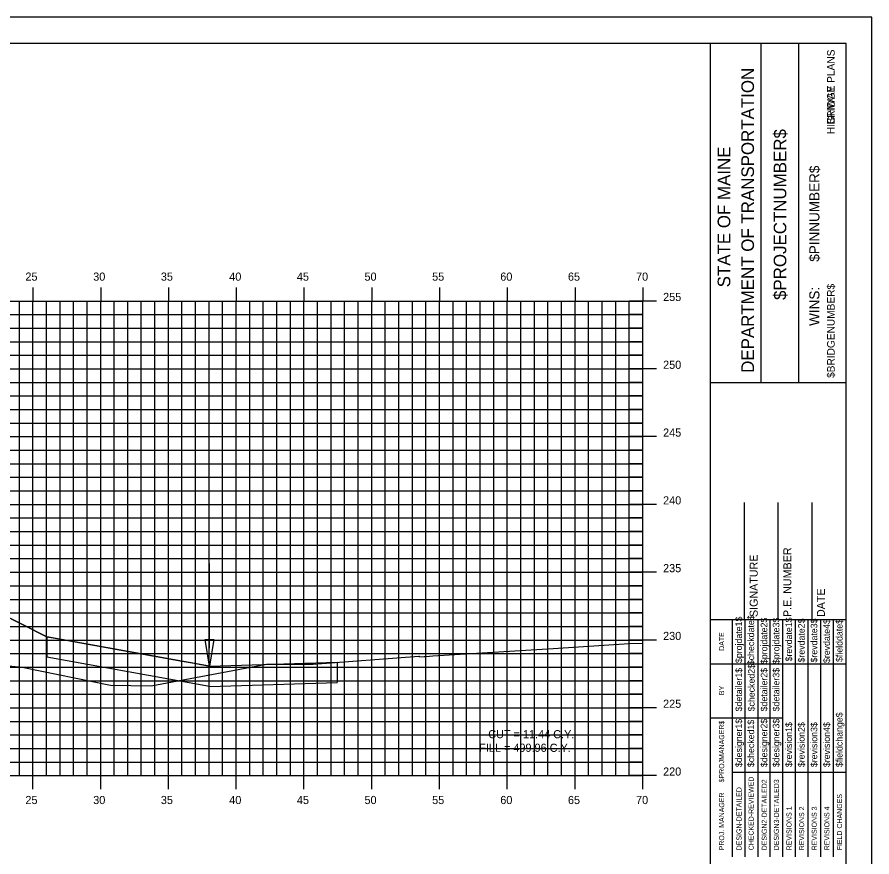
# Model space of a CAD drawing. Extents: x -22 to 1480, y -1511 to 8.
# Drawn here: x 877.3 to 940.3, y -1463.3 to -1401.4 of the extents above; entities that cross this region are included whole.
import ezdxf

# ---------------------------------------------------------------- set-up
doc = ezdxf.new("R2010")
doc.units = 0
for name, color, linetype in [('ANNOTATION', 7, 'Continuous'), ('BORDER', 7, 'Continuous'), ('BRIDGE_TITLE', 7, 'Continuous'), ('D_Drainage_Ditch_Line', 7, 'Continuous'), ('D_Roadway_Centerline', 7, 'Continuous'), ('D_Roadway_SlopeLines', 7, 'Continuous'), ('H_V ANNOTATION', 7, 'Continuous'), ('HIGHWAY_TITLE', 7, 'Continuous'), ('MAJOR', 7, 'Continuous'), ('MINOR', 7, 'Continuous'), ('PLOT BOUNDARY', 7, 'Continuous'), ('S_Roadway_Centerline', 7, 'Continuous')]:
    doc.layers.add(name, color=color, linetype=linetype)

msp = doc.modelspace()

# ---------------------------------------------------------------- linework, layer by layer
at = {"layer": 'BORDER'}
for p, q in [((938.426, -1403.331), (778.426, -1403.331)), ((928.426, -1508.328), (928.426, -1403.328)), ((932.155, -1428.334), (932.155, -1403.334)), ((934.95, -1428.334), (934.95, -1403.334)), ((938.426, -1508.328), (938.426, -1403.328)), ((928.427, -1428.337), (938.426, -1428.337)), ((930.926, -1445.828), (930.926, -1437.181)), ((933.426, -1445.828), (933.426, -1437.181)), ((935.926, -1445.828), (935.926, -1437.181)), ((928.426, -1445.828), (938.426, -1445.828))]:
    msp.add_line(p, q, dxfattribs=at)
for points in [[(930.041, -1449.078), (930.041, -1445.828)], [(930.974, -1463.325), (930.974, -1445.828)], [(931.905, -1445.828), (931.905, -1463.325)], [(932.837, -1463.325), (932.837, -1445.828)], [(933.769, -1463.325), (933.769, -1445.828)], [(934.7, -1463.325), (934.7, -1445.828)], [(935.632, -1463.325), (935.632, -1445.828)], [(936.564, -1463.325), (936.564, -1445.828)], [(937.495, -1463.325), (937.495, -1445.828)], [(930.042, -1463.325), (930.042, -1446.534)], [(928.426, -1449.078), (938.426, -1449.078)], [(928.426, -1453.078), (930.042, -1453.078)], [(930.041, -1453.078), (933.768, -1453.078)], [(930.041, -1457.078), (938.426, -1457.078)]]:
    msp.add_lwpolyline(points, dxfattribs=at)
at = {"layer": 'D_Drainage_Ditch_Line'}
msp.add_line((891.456, -1447.94), (891.456, -1441.697), dxfattribs=at)
msp.add_lwpolyline([(891.128, -1447.284), (891.784, -1447.284), (891.456, -1449.252)], close=True, dxfattribs=at)
at = {"layer": 'D_Roadway_Centerline'}
msp.add_lwpolyline([(874.083, -1444.402), (879.451, -1447.086), (880.06, -1447.196), (885.062, -1448.098), (889.433, -1448.888), (890.33, -1449.05), (891.456, -1449.252), (900.867, -1448.972)], dxfattribs=at)
at = {"layer": 'D_Roadway_SlopeLines'}
for p, q in [((879.451, -1447.086), (874.083, -1444.402)), ((879.451, -1447.086), (879.451, -1448.586)), ((900.867, -1448.972), (900.867, -1450.47)), ((891.456, -1450.752), (900.867, -1450.47))]:
    msp.add_line(p, q, dxfattribs=at)
for points in [[(891.456, -1449.252), (879.451, -1447.086)], [(891.456, -1449.252), (879.451, -1447.086)], [(891.456, -1450.752), (879.451, -1448.586)]]:
    msp.add_lwpolyline(points, dxfattribs=at)
at = {"layer": 'MAJOR'}
for p, q in [((878.426, -1421.329), (878.426, -1422.331)), ((883.426, -1421.329), (883.426, -1422.331)), ((888.426, -1421.329), (888.426, -1422.331)), ((893.426, -1421.329), (893.426, -1422.331)), ((898.426, -1421.329), (898.426, -1422.331)), ((903.426, -1421.329), (903.426, -1422.331)), ((908.426, -1421.329), (908.426, -1422.331)), ((913.426, -1421.329), (913.426, -1422.331)), ((918.426, -1421.329), (918.426, -1422.331)), ((923.426, -1421.329), (923.426, -1422.331)), ((783.426, -1422.331), (923.426, -1422.331)), ((783.426, -1422.331), (923.426, -1422.331)), ((878.426, -1457.331), (878.426, -1422.331)), ((883.426, -1457.331), (883.426, -1422.331)), ((888.426, -1457.331), (888.426, -1422.331)), ((893.426, -1457.331), (893.426, -1422.331)), ((898.426, -1457.331), (898.426, -1422.331)), ((903.426, -1457.331), (903.426, -1422.331)), ((908.426, -1457.331), (908.426, -1422.331)), ((913.426, -1457.331), (913.426, -1422.331)), ((918.426, -1457.331), (918.426, -1422.331)), ((924.428, -1422.331), (922.424, -1422.331)), ((923.426, -1457.331), (923.426, -1422.331)), ((923.426, -1457.331), (923.426, -1422.331)), ((783.426, -1427.331), (923.426, -1427.331)), ((924.428, -1427.331), (922.424, -1427.331)), ((783.426, -1432.331), (923.426, -1432.331)), ((924.428, -1432.331), (922.424, -1432.331)), ((783.426, -1437.331), (923.426, -1437.331)), ((924.428, -1437.331), (922.424, -1437.331)), ((783.426, -1442.331), (923.426, -1442.331)), ((924.428, -1442.331), (922.424, -1442.331)), ((783.426, -1447.331), (923.426, -1447.331)), ((924.428, -1447.331), (922.424, -1447.331)), ((783.426, -1452.331), (923.426, -1452.331)), ((924.428, -1452.331), (922.424, -1452.331)), ((783.426, -1457.331), (923.426, -1457.331)), ((783.426, -1457.331), (923.426, -1457.331)), ((878.426, -1458.333), (878.426, -1457.331)), ((883.426, -1458.333), (883.426, -1457.331)), ((888.426, -1458.333), (888.426, -1457.331)), ((893.426, -1458.333), (893.426, -1457.331)), ((898.426, -1458.333), (898.426, -1457.331)), ((903.426, -1458.333), (903.426, -1457.331)), ((908.426, -1458.333), (908.426, -1457.331)), ((913.426, -1458.333), (913.426, -1457.331)), ((918.426, -1458.333), (918.426, -1457.331)), ((924.428, -1457.331), (922.424, -1457.331)), ((923.426, -1458.333), (923.426, -1457.331))]:
    msp.add_line(p, q, dxfattribs=at)
at = {"layer": 'MINOR'}
for p, q in [((877.426, -1457.331), (877.426, -1422.331)), ((879.426, -1457.331), (879.426, -1422.331)), ((880.426, -1457.331), (880.426, -1422.331)), ((881.426, -1457.331), (881.426, -1422.331)), ((882.426, -1457.331), (882.426, -1422.331)), ((884.426, -1457.331), (884.426, -1422.331)), ((885.426, -1457.331), (885.426, -1422.331)), ((886.426, -1457.331), (886.426, -1422.331)), ((887.426, -1457.331), (887.426, -1422.331)), ((889.426, -1457.331), (889.426, -1422.331)), ((890.426, -1457.331), (890.426, -1422.331)), ((891.426, -1457.331), (891.426, -1422.331)), ((892.426, -1457.331), (892.426, -1422.331)), ((894.426, -1457.331), (894.426, -1422.331)), ((895.426, -1457.331), (895.426, -1422.331)), ((896.426, -1457.331), (896.426, -1422.331)), ((897.426, -1457.331), (897.426, -1422.331)), ((899.426, -1457.331), (899.426, -1422.331)), ((900.426, -1457.331), (900.426, -1422.331)), ((901.426, -1457.331), (901.426, -1422.331)), ((902.426, -1457.331), (902.426, -1422.331)), ((904.426, -1457.331), (904.426, -1422.331)), ((905.426, -1457.331), (905.426, -1422.331)), ((906.426, -1457.331), (906.426, -1422.331)), ((907.426, -1457.331), (907.426, -1422.331)), ((909.426, -1457.331), (909.426, -1422.331)), ((910.426, -1457.331), (910.426, -1422.331)), ((911.426, -1457.331), (911.426, -1422.331)), ((912.426, -1457.331), (912.426, -1422.331)), ((914.426, -1457.331), (914.426, -1422.331)), ((915.426, -1457.331), (915.426, -1422.331)), ((916.426, -1457.331), (916.426, -1422.331)), ((917.426, -1457.331), (917.426, -1422.331)), ((919.426, -1457.331), (919.426, -1422.331)), ((920.426, -1457.331), (920.426, -1422.331)), ((921.426, -1457.331), (921.426, -1422.331)), ((922.426, -1457.331), (922.426, -1422.331)), ((783.426, -1423.331), (923.426, -1423.331)), ((923.426, -1423.331), (922.424, -1423.331)), ((783.426, -1424.331), (923.426, -1424.331)), ((923.426, -1424.331), (922.424, -1424.331)), ((783.426, -1425.331), (923.426, -1425.331)), ((923.426, -1425.331), (922.424, -1425.331)), ((783.426, -1426.331), (923.426, -1426.331)), ((923.426, -1426.331), (922.424, -1426.331)), ((783.426, -1428.331), (923.426, -1428.331)), ((923.426, -1428.331), (922.424, -1428.331)), ((783.426, -1429.331), (923.426, -1429.331)), ((923.426, -1429.331), (922.424, -1429.331)), ((783.426, -1430.331), (923.426, -1430.331)), ((923.426, -1430.331), (922.424, -1430.331)), ((783.426, -1431.331), (923.426, -1431.331)), ((923.426, -1431.331), (922.424, -1431.331)), ((783.426, -1433.331), (923.426, -1433.331)), ((923.426, -1433.331), (922.424, -1433.331)), ((783.426, -1434.331), (923.426, -1434.331)), ((923.426, -1434.331), (922.424, -1434.331)), ((783.426, -1435.331), (923.426, -1435.331)), ((923.426, -1435.331), (922.424, -1435.331)), ((783.426, -1436.331), (923.426, -1436.331)), ((923.426, -1436.331), (922.424, -1436.331)), ((783.426, -1438.331), (923.426, -1438.331)), ((923.426, -1438.331), (922.424, -1438.331)), ((783.426, -1439.331), (923.426, -1439.331)), ((923.426, -1439.331), (922.424, -1439.331)), ((783.426, -1440.331), (923.426, -1440.331)), ((923.426, -1440.331), (922.424, -1440.331)), ((783.426, -1441.331), (923.426, -1441.331)), ((923.426, -1441.331), (922.424, -1441.331)), ((783.426, -1443.331), (923.426, -1443.331)), ((923.426, -1443.331), (922.424, -1443.331)), ((783.426, -1444.331), (923.426, -1444.331)), ((923.426, -1444.331), (922.424, -1444.331)), ((783.426, -1445.331), (923.426, -1445.331)), ((923.426, -1445.331), (922.424, -1445.331)), ((783.426, -1446.331), (923.426, -1446.331)), ((923.426, -1446.331), (922.424, -1446.331)), ((783.426, -1448.331), (923.426, -1448.331)), ((923.426, -1448.331), (922.424, -1448.331)), ((783.426, -1449.331), (923.426, -1449.331)), ((923.426, -1449.331), (922.424, -1449.331)), ((783.426, -1450.331), (923.426, -1450.331)), ((923.426, -1450.331), (922.424, -1450.331)), ((783.426, -1451.331), (923.426, -1451.331)), ((923.426, -1451.331), (922.424, -1451.331)), ((783.426, -1453.331), (923.426, -1453.331)), ((923.426, -1453.331), (922.424, -1453.331)), ((783.426, -1454.331), (923.426, -1454.331)), ((923.426, -1454.331), (922.424, -1454.331)), ((783.426, -1455.331), (923.426, -1455.331)), ((923.426, -1455.331), (922.424, -1455.331)), ((783.426, -1456.331), (923.426, -1456.331)), ((923.426, -1456.331), (922.424, -1456.331))]:
    msp.add_line(p, q, dxfattribs=at)
at = {"layer": 'PLOT BOUNDARY'}
msp.add_lwpolyline([(770.333, -1511.39), (940.333, -1511.39), (940.333, -1401.39), (770.333, -1401.39)], close=True, dxfattribs=at)
at = {"layer": 'S_Roadway_Centerline'}
msp.add_lwpolyline([(873.038, -1448.9), (877.633, -1449.335), (884.159, -1450.673), (887.145, -1450.704), (895.653, -1449.11), (899.11, -1449.102), (906.906, -1448.528), (906.939, -1448.533), (906.966, -1448.562), (907.287, -1448.547), (907.447, -1448.536), (907.929, -1448.503), (907.932, -1448.503), (916.802, -1447.957), (922.425, -1447.583), (923.426, -1447.574)], dxfattribs=at)
msp.add_lwpolyline([(873.038, -1448.9), (877.633, -1449.335), (884.159, -1450.673), (887.145, -1450.704), (895.653, -1449.11), (899.11, -1449.102), (906.906, -1448.528), (906.939, -1448.533), (906.966, -1448.562), (907.287, -1448.547), (907.447, -1448.536), (907.929, -1448.503), (907.932, -1448.503), (916.802, -1447.957), (922.425, -1447.583), (923.426, -1447.574)], dxfattribs=at)

# ---------------------------------------------------------------- texts
at = {"layer": 'ANNOTATION'}
for s, p in [('CUT = 11.44 C.Y.', (912.024, -1454.571)), ('FILL = 499.96 C.Y.', (911.359, -1455.572))]:
    msp.add_text(s, height=0.6, rotation=359.92408, dxfattribs=at).set_placement(p)
at = {"layer": 'BORDER'}
for s, height, p in [('DEPARTMENT OF TRANSPORTATION', 0.93176, (931.633, -1427.625)), ('$PROJECTNUMBER$', 0.93176, (934.018, -1422.252)), ('STATE OF MAINE', 0.93176, (929.882, -1421.319)), ('$PINNUMBER$', 0.74527, (936.463, -1419.434)), ('WINS:', 0.7453, (936.461, -1424.164)), ('P.E. NUMBER', 0.59055, (934.387, -1445.636)), ('SIGNATURE', 0.5906, (931.907, -1445.636)), ('DATE', 0.5906, (936.867, -1445.636)), ('$projdate1$', 0.48455, (930.749, -1449.028)), ('$checkdate$', 0.48455, (931.644, -1449.186)), ('$projdate2$', 0.48455, (932.613, -1449.107)), ('$projdate3$', 0.48455, (933.507, -1449.107)), ('$revdate1$', 0.4845, (934.439, -1448.91)), ('$revdate2$', 0.4845, (935.37, -1448.989)), ('$revdate3$', 0.4845, (936.302, -1448.989)), ('$revdate4$', 0.4845, (937.234, -1449.028)), ('$fielddate$', 0.48455, (938.165, -1448.949)), ('DATE', 0.3714, (929.431, -1448.123)), ('$detailer1$', 0.48455, (930.749, -1452.593)), ('$checked2$', 0.4845, (931.681, -1452.593)), ('$detailer2$', 0.48455, (932.613, -1452.593)), ('$detailer3$', 0.48455, (933.507, -1452.593)), ('BY', 0.3714, (929.431, -1451.393)), ('$designer1$', 0.48455, (930.749, -1456.705)), ('$designer2$', 0.48455, (932.613, -1456.705)), ('$designer3$', 0.48455, (933.507, -1456.705)), ('$fieldchange$', 0.48455, (938.165, -1456.705)), ('$PROJMANAGER$', 0.37275, (929.431, -1457.833)), ('$checked1$', 0.4845, (931.644, -1456.705)), ('$revision1$', 0.48455, (934.439, -1456.705)), ('$revision2$', 0.48455, (935.37, -1456.705)), ('$revision3$', 0.48455, (936.302, -1456.705)), ('$revision4$', 0.48455, (937.234, -1456.705)), ('CHECKED-REVIEWED', 0.37275, (931.607, -1462.84)), ('DESIGN2-DETAILED2', 0.37275, (932.576, -1462.84)), ('DESIGN3-DETAILED3', 0.37275, (933.471, -1462.84)), ('PROJ. MANAGER', 0.37275, (929.431, -1462.84)), ('DESIGN-DETAILED', 0.37275, (930.713, -1462.84)), ('FIELD CHANGES', 0.37275, (938.129, -1462.84)), ('REVISIONS 1', 0.37275, (934.402, -1462.84)), ('REVISIONS 2', 0.37275, (935.334, -1462.84)), ('REVISIONS 3', 0.37275, (936.266, -1462.84)), ('REVISIONS 4', 0.37275, (937.197, -1462.84))]:
    msp.add_text(s, height=height, rotation=90, dxfattribs=at).set_placement(p)
at = {"layer": 'BRIDGE_TITLE'}
for s, p in [('BRIDGE PLANS', (937.585, -1409.307)), ('$BRIDGENUMBER$', (937.585, -1428.001))]:
    msp.add_text(s, height=0.55901, rotation=90, dxfattribs=at).set_placement(p)
at = {"layer": 'H_V ANNOTATION'}
for s, p in [('25', (877.872, -1420.831)), ('30', (882.875, -1420.831)), ('35', (887.867, -1420.831)), ('40', (892.912, -1420.831)), ('45', (897.904, -1420.831)), ('50', (902.891, -1420.831)), ('55', (907.883, -1420.831)), ('60', (912.912, -1420.831)), ('65', (917.904, -1420.831)), ('70', (922.928, -1420.831)), ('255', (924.926, -1422.331)), ('250', (924.926, -1427.331)), ('245', (924.926, -1432.331)), ('240', (924.926, -1437.331)), ('235', (924.926, -1442.331)), ('230', (924.926, -1447.331)), ('225', (924.926, -1452.331)), ('220', (924.926, -1457.331)), ('25', (877.872, -1459.431)), ('30', (882.875, -1459.431)), ('35', (887.867, -1459.431)), ('40', (892.912, -1459.431)), ('45', (897.904, -1459.431)), ('50', (902.891, -1459.431)), ('55', (907.883, -1459.431)), ('60', (912.912, -1459.431)), ('65', (917.904, -1459.431)), ('70', (922.928, -1459.431))]:
    msp.add_text(s, height=0.6, dxfattribs=at).set_placement(p)
at = {"layer": 'HIGHWAY_TITLE'}
msp.add_text('HIGHWAY PLANS', height=0.55901, rotation=90, dxfattribs=at).set_placement((937.585, -1410.016))

doc.saveas('drawing.dxf')
